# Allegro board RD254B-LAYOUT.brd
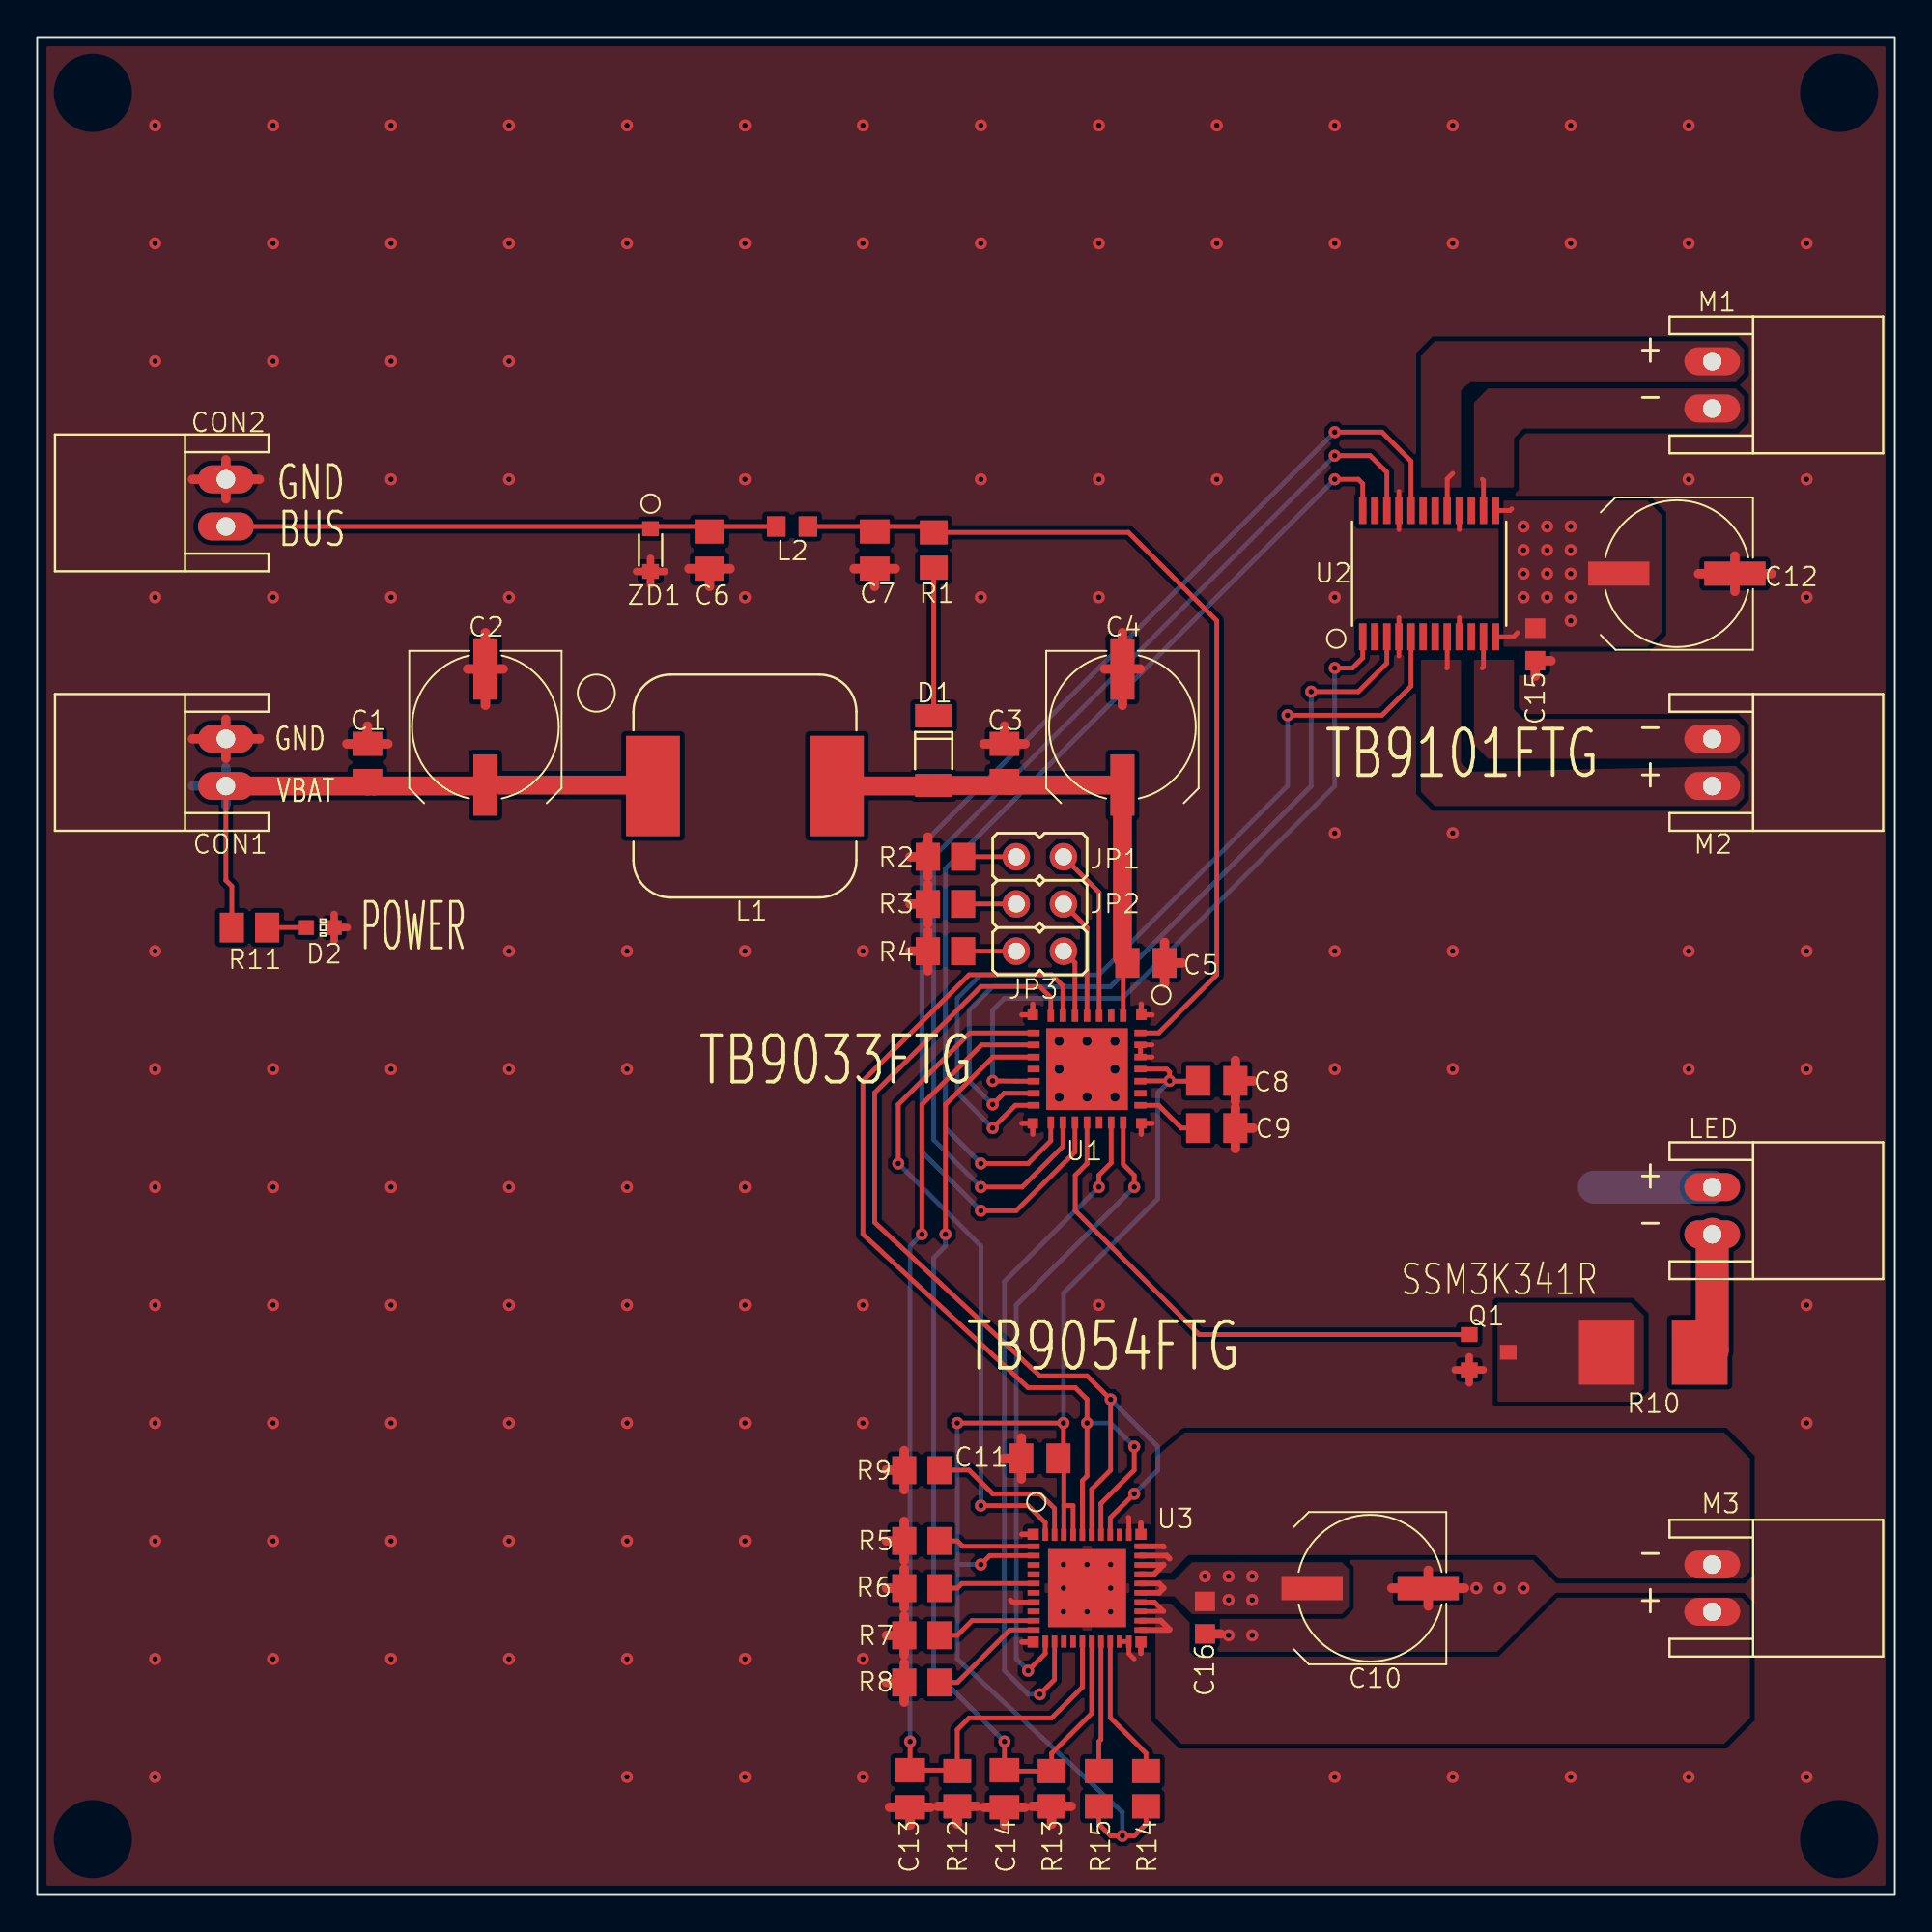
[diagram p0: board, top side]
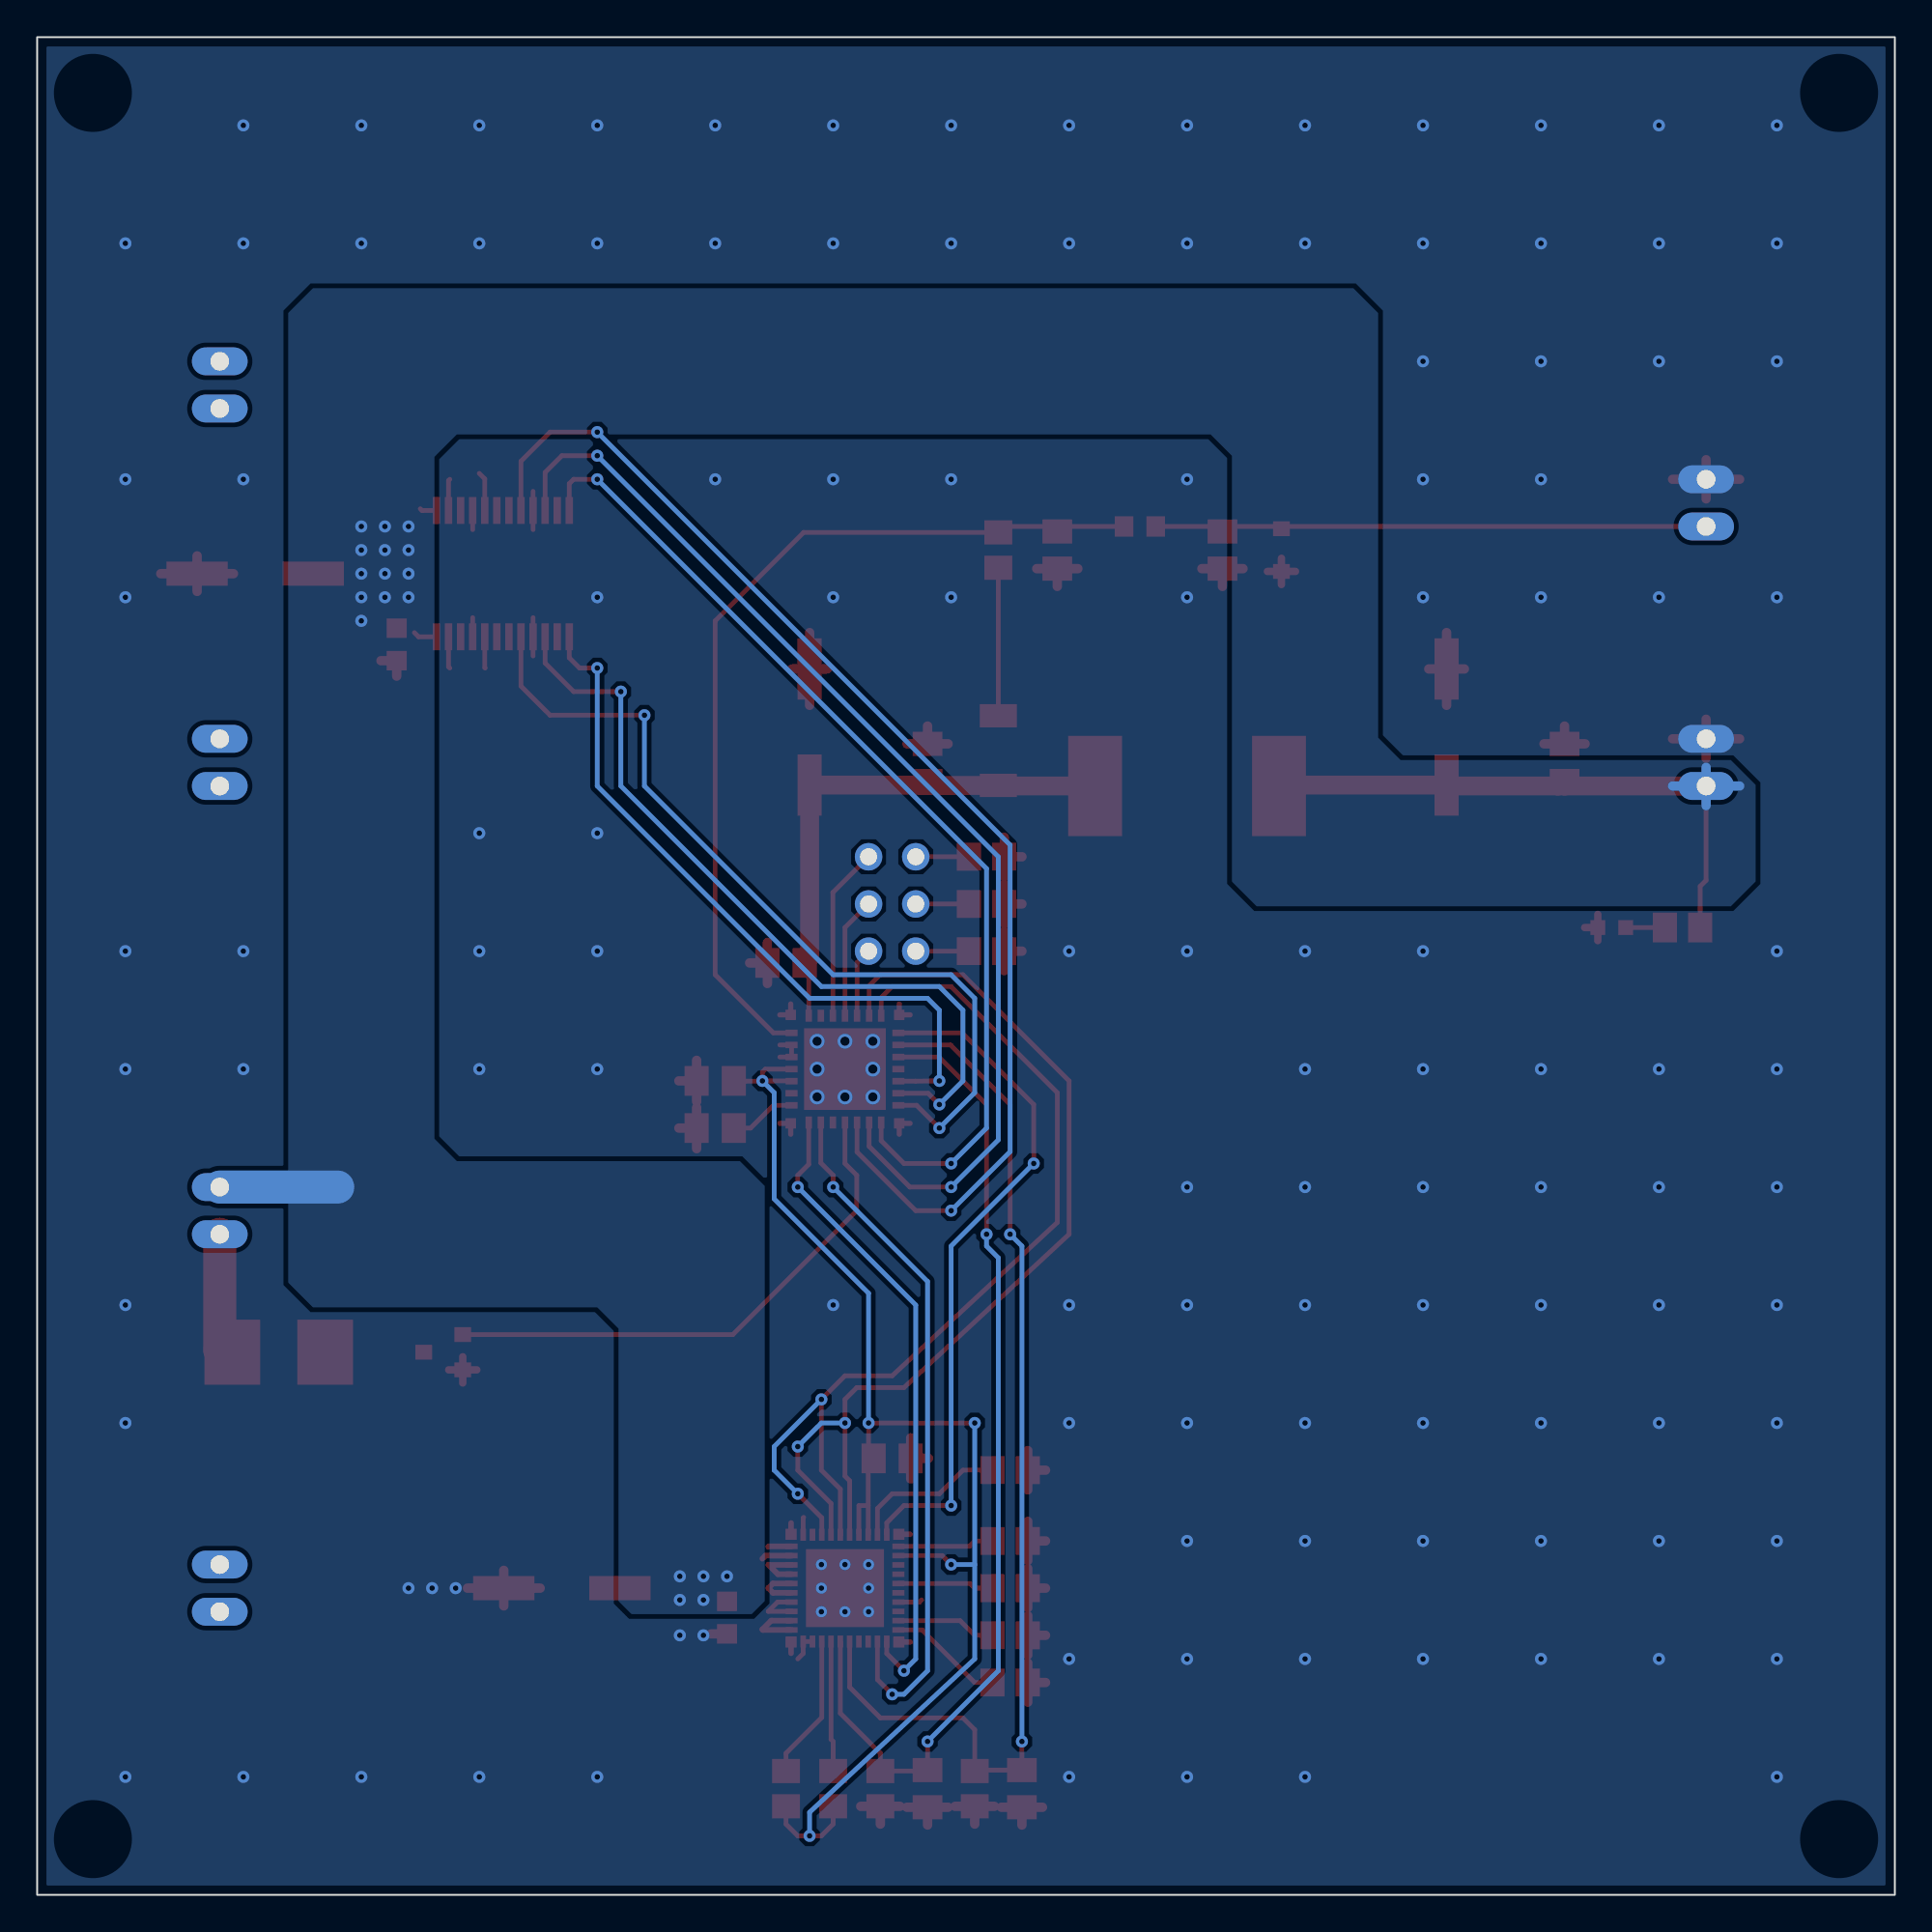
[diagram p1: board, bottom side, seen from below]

Outline 100 x 100 mm; copper layers: TOP, BOTTOM. Coordinates in mm from the lower left corner of the outline.
Outline path: rectangle 0,0 100,100

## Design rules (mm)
constraint set DEFAULT: 

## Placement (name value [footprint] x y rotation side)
C1  -  [C0805K]  17.78 60.96 90 top
C2  -  [UD_8X10_NICHICON_01]  24.13 62.87 270 top
C3  -  [C0805K]  52.07 60.96 90 top
C4  -  [UD_8X10_NICHICON_01]  58.42 62.87 270 top
C5  -  [C0805K]  59.69 50.16 0 top
C6  -  [C0805K]  36.2 72.39 270 top
C7  -  [C0805K]  45.09 72.39 270 top
C8  -  [C0805K]  63.5 43.81 180 top
C9  -  [C0805K]  63.5 41.27 180 top
C10  -  [UD_8X10_NICHICON_01]  71.75 16.51 180 top
C11  -  [C0805K]  53.98 23.5 0 top
C12  -  [UD_8X10_NICHICON_01]  88.27 71.12 180 top
C13  -  [C0805K]  46.99 5.71 270 top
C14  -  [C0805K]  52.07 5.71 270 top
C15  -  [C0603K]  80.64 67.31 270 top
C16  -  [C0603K]  62.87 14.92 270 top
CON1  -  [S2B_XH_A]  10.16 60.96 90 top
CON2  -  [S2B_XH_A]  10.16 74.93 90 top
CON3  -  [S2B_XH_A]  90.17 81.28 270 top
CON4  -  [S2B_XH_A]  90.17 60.96 270 top
CON5  -  [S2B_XH_A]  90.17 16.51 270 top
CON6  -  [S2B_XH_A]  90.17 36.83 270 top
D1  -  [LL4148]  48.26 61.59 90 top
D2  -  [CHIP_LED0603]  15.24 52.07 270 top
JP1  -  [JP1]  53.98 55.88 270 top
JP2  -  [JP1]  53.98 53.34 270 top
JP3  -  [JP1]  53.98 50.8 270 top
L1  -  [7447709222]  38.1 59.69 270 top
L2  -  [R0603]  40.64 73.66 0 top
NOREF  -  []  -70 -47 0 top
Q1  -  [SOT_23F]  78.74 29.21 270 top
R1  -  [R0805]  48.26 72.39 270 top
R2  -  [R0805]  48.9 55.88 180 top
R3  -  [R0805]  48.9 53.34 180 top
R4  -  [R0805]  48.9 50.8 180 top
R5  -  [R0805]  47.62 19.05 180 top
R6  -  [R0805]  47.62 16.51 180 top
R7  -  [R0805]  47.62 13.97 180 top
R8  -  [R0805]  47.62 11.43 180 top
R9  -  [R0805]  47.62 22.86 180 top
R10  -  [R2512_2010]  87 29.21 0 top
R11  -  [M0805]  11.43 52.07 180 top
R12  -  [R0805]  49.53 5.71 270 top
R13  -  [R0805]  54.61 5.71 270 top
R14  -  [R0805]  59.69 5.71 90 top
R15  -  [R0805]  57.15 5.71 90 top
U1  -  [P_VQFN28_0606_0_65_003_01]  56.52 44.45 180 top
U2  -  [SSOP24_P_300_0_65A]  74.93 71.12 90 top
U3  -  [P_VQFN40_0606_0_50_001_01]  56.52 16.51 270 top
ZD1  -  [USC]  33.02 72.39 270 top

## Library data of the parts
C1 C3 C5-C9 C11 C13 C14 = C0805K: alternate symbols: (T:C0805K,C1_C0805K,C3_C0805K,C5_C0805K,C6_C0805K,C7_C0805K,C8_C0805K,C9_C0805K,C11_C0805K,C13_C0805K,C14_C0805K;B:C0805K_bk)
C2 C4 C10 C12 = UD-8X10_NICHICON_01: alternate symbols: (T:UD_8X10_NICHICON_01,C2_UD_8X10_NICHICON_01,C4_UD_8X10_NICHICON_01,C10_UD_8X10_NICHICON_01,C12_UD_8X10_NICHICON_01;B:UD_8X10_NICHICON_01_bk)
C15 C16 = C0603K: alternate symbols: (T:C0603K,C15_C0603K,C16_C0603K;B:C0603K_bk)
CON1-CON6 = S2B-XH-A: alternate symbols: (T:S2B_XH_A,CON1_S2B_XH_A,CON2_S2B_XH_A,CON3_S2B_XH_A;B:S2B_XH_A_bk)
D1 = LL4148: alternate symbols: (T:LL4148;B:LL4148_bk)
D2 = CHIP-LED0603: alternate symbols: (T:CHIP_LED0603,D2_CHIP_LED0603;B:CHIP_LED0603_bk)
JP1-JP3 = JP1: alternate symbols: (T:JP1,JP1_JP1,JP2_JP1,JP3_JP1;B:JP1_bk)
L1 = 7447709222: alternate symbols: (T:7447709222;B:7447709222_bk)
L2 = R0603: alternate symbols: (T:R0603,L2_R0603;B:R0603_bk)
Q1 = SOT-23F: alternate symbols: (T:SOT_23F;B:SOT_23F_bk)
R1-R9 R12-R15 = R0805: alternate symbols: (T:R0805,R12_R0805,R13_R0805,R14_R0805,R15_R0805,R1_R0805,R2_R0805,R3_R0805,R4_R0805,R5_R0805,R6_R0805,R7_R0805,R8_R0805,R9_R0805;B:R0805_bk)
R10 = R2512-2010: alternate symbols: (T:R2512_2010,R10_R2512_2010;B:R2512_2010_bk)
R11 = M0805: alternate symbols: (T:M0805,R11_M0805;B:M0805_bk)
U1 = P-VQFN28-0606-0_65-003_01: alternate symbols: (T:P_VQFN28_0606_0_65_003_01,U1_P_VQFN28_0606_0_65_003_01;B:P_VQFN28_0606_0_65_003_01_bk)
U2 = SSOP24-P-300-0_65A: alternate symbols: (T:SSOP24_P_300_0_65A;B:SSOP24_P_300_0_65A_bk)
U3 = P-VQFN40-0606-0_50-001_01: alternate symbols: (T:P_VQFN40_0606_0_50_001_01,U3_P_VQFN40_0606_0_50_001_01;B:P_VQFN40_0606_0_50_001_01_bk)
ZD1 = USC: alternate symbols: (T:USC;B:USC_bk)

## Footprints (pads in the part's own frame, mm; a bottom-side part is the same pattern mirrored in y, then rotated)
7447709222
  rect 5.4x2.9 smd: 1(0,-4.95) 2(0,4.95)
C0603K
  rect 1.05x1.08 smd: 1(-0.875,0) 2(0.875,0)
C0805K
  rect 1.3x1.6 smd: 1(-1,0) 2(1,0)
CHIP_LED0603
  rect 0.8x0.8 smd: A(0,-0.75) C(0,0.75)
JP1
  round 1.48 hole 0.914: 1(0,-1.27) 2(0,1.27)
LL4148
  rect 1.25x2 smd: A(-1.875,0) K(1.875,0)
M0805
  rect 1.3x1.6 smd: 1(-0.95,0) 2(0.95,0)
P_VQFN28_0606_0_65_003_01
  rect 0.35x0.65 smd: 1(-1.95,-2.875) 2(-1.3,-2.875) 3(-0.65,-2.875) 4(0,-2.875) 5(0.65,-2.875) 6(1.3,-2.875) 7(1.95,-2.875) 15(1.95,2.875) 16(1.3,2.875) 17(0.65,2.875) 18(0,2.875) 19(-0.65,2.875) 20(-1.3,2.875) 21(-1.95,2.875)
  rect 0.56x0.56 smd: 1T(-2.92,-2.92) 2T(2.92,-2.92) 3T(2.92,2.92) 4T(-2.92,2.92)
  rect 0.65x0.35 smd: 8(2.875,-1.95) 9(2.875,-1.3) 10(2.875,-0.65) 11(2.875,0) 12(2.875,0.65) 13(2.875,1.3) 14(2.875,1.95) 22(-2.875,1.95) 23(-2.875,1.3) 24(-2.875,0.65) 25(-2.875,0) 26(-2.875,-0.65) 27(-2.875,-1.3) 28(-2.875,-1.95)
  rect 4.4x4.4 smd: E_PAD(0,0)
P_VQFN40_0606_0_50_001_01
  rect 0.3x0.65 smd: 1(-2.25,-2.875) 2(-1.75,-2.875) 3(-1.25,-2.875) 4(-0.75,-2.875) 5(-0.25,-2.875) 6(0.25,-2.875) 7(0.75,-2.875) 8(1.25,-2.875) 9(1.75,-2.875) 10(2.25,-2.875) 21(2.25,2.875) 22(1.75,2.875) 23(1.25,2.875) 24(0.75,2.875) 25(0.25,2.875) 26(-0.25,2.875) 27(-0.75,2.875) 28(-1.25,2.875) 29(-1.75,2.875) 30(-2.25,2.875)
  rect 0.6x0.6 smd: 1T(2.9,-2.9) 2T(2.9,2.9) 3T(-2.9,2.9) 4T(-2.9,-2.9)
  rect 0.65x0.3 smd: 11(2.875,-2.25) 12(2.875,-1.75) 13(2.875,-1.25) 14(2.875,-0.75) 15(2.875,-0.25) 16(2.875,0.25) 17(2.875,0.75) 18(2.875,1.25) 19(2.875,1.75) 20(2.875,2.25) 31(-2.875,2.25) 32(-2.875,1.75) 33(-2.875,1.25) 34(-2.875,0.75) 35(-2.875,0.25) 36(-2.875,-0.25) 37(-2.875,-0.75) 38(-2.875,-1.25) 39(-2.875,-1.75) 40(-2.875,-2.25)
  rect 4.2x4.2 smd: E_PAD(0,0)
R0603
  rect 1x1.1 smd: 1(-0.85,0) 2(0.85,0)
R0805
  rect 1.3x1.5 smd: 1(-0.95,0) 2(0.95,0)
R2512_2010
  rect 3x3.5 smd: P_1(-2.5,0) P_2(2.5,0)
S2B_XH_A
  oval 1.5x3 hole 1: 1(1.27,0) 2(-1.27,0)
SOT_23F
  rect 0.8x0.9 smd: 1(-0.95,-1.65) 2(0.95,-1.65) 3(0,0.45)
SSOP24_P_300_0_65A
  rect 1.45x0.4 smd: 1(-3.4,3.575) 2(-3.4,2.925) 3(-3.4,2.275) 4(-3.4,1.625) 5(-3.4,0.975) 6(-3.4,0.325) 7(-3.4,-0.325) 8(-3.4,-0.975) 9(-3.4,-1.625) 10(-3.4,-2.275) 11(-3.4,-2.925) 12(-3.4,-3.575) 13(3.4,-3.575) 14(3.4,-2.925) 15(3.4,-2.275) 16(3.4,-1.625) 17(3.4,-0.975) 18(3.4,-0.325) 19(3.4,0.325) 20(3.4,0.975) 21(3.4,1.625) 22(3.4,2.275) 23(3.4,2.925) 24(3.4,3.575)
UD_8X10_NICHICON_01
  rect 3.3x1.3 smd: 1(-3.125,0) 2(3.125,0)
USC
  rect 0.8x0.9 smd: 1(-1.15,0) 2(1.15,0)

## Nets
+12V: C1.1 C2.2 C10.2 C12.2 C15.1 C16.1 CON1.2 CON6.2 L1.1 R11.2 U2.12 U2.13 U3.25 U3.26
GND: C1.2 C2.1 C3.2 C4.1 C5.2 C6.2 C7.2 C8.1 C9.1 C10.1 C11.1 C12.1 C13.2 C14.2 C15.2 C16.2 CON1.1 CON2.1 D2.C Q1.2 R2.2 R3.2 R4.2 R5.2 R6.2 R7.2 R8.2 R9.2 R12.2 R13.2 U1.1T U1.2T U1.3T U1.4T U1.26 U1.27 U1.E_PAD U2.4 U2.9 U2.16 U2.21 U3.1T U3.2T U3.3T U3.4T U3.7 U3.19 U3.20 U3.31 U3.32 U3.E_PAD ZD1.2
VCC: C8.2 C11.2 R14.1 R15.1 U1.24 U1.25 U3.2 U3.37 U3.38
VDD: C9.2 U1.22
BUS: C3.1 C4.2 C5.1 C6.1 C7.1 CON2.2 D1.A D1.K L1.2 L2.1 L2.2 R1.1 R1.2 U1.1 U1.28 ZD1.1
N_2: JP3.1 JP3.2 R4.1 U1.5
N_3: JP2.1 JP2.2 R3.1 U1.4
N_4: JP1.1 JP1.2 R2.1 U1.3
N_5: R5.1 U3.1
N_6: R6.1 U3.5
N_7: R7.1 U3.9
N_8: R8.1 U3.10
N_9: CON4.1 U2.8
N_10: CON5.2 U3.27 U3.28 U3.29 U3.30
N_11: CON5.1 U3.21 U3.22 U3.23 U3.24
N_12: U1.7 U3.33 U3.35
N_13: U1.6 U3.34 U3.36
N_14: U1.8 U3.40
N_15: R9.1 U3.39
N_16: CON4.2 U2.11
N_17: C13.1 R12.1 U1.9 U3.15
N_18: C14.1 R13.1 U1.10 U3.16
N_19: U1.21 U3.11
N_20: U1.20 U3.12
N_21: CON6.1 R10.P_2
N_22: U1.14 U2.5
N_23: U1.13 U2.3
N_24: U1.12 U2.1
N_25: U1.15 U2.24
N_26: U1.16 U2.22
N_27: U1.17 U2.20
N_28: CON3.1 U2.14
N_29: CON3.2 U2.17
N_30: D2.A R11.1
N_31: Q1.3 R10.P_1
N_32: Q1.1 U1.18
N_36: R14.2 U3.18
N_37: R15.2 U3.17

Pads without a net: U1 2 11 19 23; U2 2 6 7 10 15 18 19 23; U3 3 4 6 8 13 14

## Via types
v1: diameter 0.65, hole 0.3, TOP to BOTTOM, 169 vias
v2: diameter 0.803, hole 0.5, TOP to BOTTOM, 8 vias
v3: diameter 0.6, hole 0.3, TOP to BOTTOM, 8 vias

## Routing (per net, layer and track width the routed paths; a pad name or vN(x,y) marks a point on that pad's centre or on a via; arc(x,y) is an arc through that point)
+12V: length 48.4
  TOP w0.254: 78.5,67.72 79.47,67.72 79.69,67.94 ; 78.5,74.52 79.28,74.52 79.38,74.61 ; CON1.2 10.16,54.61 10.48,54.29 R11.2
  TOP w0.305: U3.26 60.39,16.76 60.64,16.51 60.39,16.26 U3.25
  TOP w1.016: L1.1 33.1,59.74 C2.2 24.08,59.69 18.14,59.69 ; 17.78,59.69 C1.1 18.14,59.69 ; 17.78,59.69 CON1.2 ; 17.78,59.69 18.14,59.69
  BOTTOM w0.5: CON1.2 11.96,59.69 ; CON1.2 10.16,58.63 ; CON1.2 10.16,60.69 ; CON1.2 8.36,59.69
  BOTTOM w1.778: CON6.2 83.82,38.1
  vias: v1(62.87,17.14) v1(64.14,17.14) v1(64.14,15.88) v1(65.41,17.14) v1(65.41,15.88) v1(80.01,73.66) v1(80.01,72.39) v1(80.01,71.12) v1(80.01,69.85) v1(81.28,73.66) v1(81.28,72.39) v1(81.28,71.12) v1(81.28,69.85) v1(82.55,73.66) v1(82.55,72.39) v1(82.55,71.12) v1(82.55,69.85) v1(82.55,68.58)
GND: length 126.5
  TOP w0.254: U3.31 58.77,20.29 58.74,20.32 ; 60.02,45.75 U1.27 U1.26 60.02,45.1 ; 73.31,75.55 U2.21 73.31,73.49 ; 76.56,73.49 U2.16 ; 59.05,12.7 58.77,12.99 U3.20 58.29,13.63 ; 73.31,66.69 U2.4 73.31,68.75 ; 52.39,15.88 52.5,15.76 U3.7 ; U2.9 76.56,68.75
  TOP w0.28: 53.01,41.53 U1.3T 53.59,40.95 ; 60.02,47.37 U1.1T 59.44,47.95 ; 53.59,47.95 U1.2T 53.01,47.37 ; 60.02,41.53 U1.4T 59.44,40.95
  TOP w0.3: 59.41,13.01 U3.2T ; U3.3T 59.41,20.02 ; 53.01,19.41 U3.4T ; 53.01,13.61 U3.1T
  TOP w0.4: 76.33,28.26 Q1.2 ; Q1.2 77.09,28.96 ; Q1.2 77.09,27.55 ; Q1.2 77.84,28.26 ; ZD1.2 33.77,71.24 ; ZD1.2 32.27,71.24 ; ZD1.2 33.02,71.94 ; ZD1.2 33.02,70.53 ; D2.C 15.99,52.77 ; D2.C 15.99,51.37 ; D2.C 16.7,52.07
  TOP w0.5: 8.36,62.23 CON1.1 ; CON1.1 10.16,61.17 ; CON1.1 10.16,63.28 ; CON1.1 11.96,62.23 ; CON2.1 11.96,76.2 ; CON2.1 10.16,77.25 ; CON2.1 10.16,75.14 ; CON2.1 8.36,76.2
  TOP w0.508: 45.72,13.97 R7.2 ; R7.2 46.67,15.03 ; R7.2 46.67,12.91 ; C12.1 93.34,71.12 ; C12.1 91.39,70.17 ; C12.1 91.39,72.08 ; C12.1 89.44,71.12 ; 45.72,22.86 R9.2 ; R9.2 46.67,21.8 ; R9.2 46.67,23.91 ; 45.72,19.05 R5.2 ; R5.2 46.67,18 ; R5.2 46.67,20.11 ; 47.95,52.28 R3.2 ; R3.2 47.95,54.4 ; R3.2 46.99,53.34 ; 16.68,61.96 C1.2 ; C1.2 18.89,61.96 ; C1.2 17.78,62.91 ; 72.92,16.51 C10.1 ; C10.1 74.88,15.55 ; C10.1 74.88,17.46 ; C10.1 76.83,16.51 ; 35.09,71.39 C6.2 ; C6.2 37.3,71.39 ; C6.2 36.2,70.44 ; C3.2 52.07,62.91 ; C3.2 50.97,61.96 ; C3.2 53.17,61.96 ; C16.2 63.71,14.05 ; C7.2 46.19,71.39 ; C7.2 45.09,70.44 ; C7.2 43.98,71.39 ; R2.2 47.95,56.94 ; R2.2 46.99,55.88 ; R2.2 47.95,54.83 ; C4.1 59.38,65.99 ; C4.1 58.42,64.03 ; C4.1 57.47,65.99 ; C4.1 58.42,67.94 ; C8.1 65.45,43.81 ; C8.1 64.5,44.92 ; C8.1 64.5,42.71 ; 47.95,49.74 R4.2 ; R4.2 46.99,50.8 ; R4.2 47.95,51.85 ; R12.2 50.59,4.76 ; R12.2 48.48,4.76 ; R12.2 49.53,3.81 ; C2.1 25.09,65.99 ; C2.1 24.13,67.94 ; C2.1 24.13,64.03 ; C2.1 23.18,65.99 ; 46.67,15.46 R6.2 ; R6.2 46.67,17.57 ; R6.2 45.72,16.51 ; 45.72,11.43 R8.2 ; R8.2 46.67,10.38 ; R8.2 46.67,12.48 ; 60.69,49.06 C5.2 ; C5.2 61.65,50.16 ; C5.2 60.69,51.27 ; C11.1 52.98,24.6 ; C11.1 52.02,23.5 ; C11.1 52.98,22.39 ; 50.97,4.71 C14.2 ; C14.2 52.07,3.76 ; C14.2 53.17,4.71 ; 54.61,3.81 R13.2 ; R13.2 55.66,4.76 ; R13.2 53.55,4.76 ; C9.1 64.5,42.38 ; C9.1 64.5,40.17 ; C9.1 65.45,41.27 ; 45.88,4.71 C13.2 ; C13.2 46.99,3.76 ; C13.2 48.09,4.71 ; 80.64,65.61 C15.2 81.49,66.44
  vias: v1(6.35,95.25) v1(6.35,88.9) v1(6.35,82.55) v1(6.35,69.85) v1(6.35,50.8) v1(6.35,44.45) v1(6.35,38.1) v1(6.35,31.75) v1(6.35,25.4) v1(6.35,19.05) v1(6.35,12.7) v1(6.35,6.35) v1(12.7,95.25) v1(12.7,88.9) v1(12.7,82.55) v1(12.7,69.85) v1(12.7,44.45) v1(12.7,38.1) v1(12.7,31.75) v1(12.7,25.4) v1(12.7,19.05) v1(12.7,12.7) v1(19.05,95.25) v1(19.05,88.9) v1(19.05,82.55) v1(19.05,76.2) v1(19.05,69.85) v1(19.05,44.45) v1(19.05,38.1) v1(19.05,31.75) v1(19.05,25.4) v1(19.05,19.05) v1(19.05,12.7) v1(25.4,95.25) v1(25.4,88.9) v1(25.4,82.55) v1(25.4,76.2) v1(25.4,69.85) v1(25.4,50.8) v1(25.4,44.45) v1(25.4,38.1) v1(25.4,31.75) v1(25.4,25.4) v1(25.4,19.05) v1(25.4,12.7) v1(31.75,95.25) v1(31.75,88.9) v1(31.75,50.8) v1(31.75,44.45) v1(31.75,38.1) v1(31.75,31.75) v1(31.75,25.4) v1(31.75,19.05) v1(31.75,12.7) v1(31.75,6.35) v1(38.1,95.25) v1(38.1,88.9) v1(38.1,76.2) v1(38.1,69.85) v1(38.1,50.8) v1(38.1,38.1) v1(38.1,31.75) v1(38.1,25.4) v1(38.1,19.05) v1(38.1,12.7) v1(38.1,6.35) v1(44.45,95.25) v1(44.45,88.9) v1(44.45,50.8) v1(44.45,31.75) v1(44.45,25.4) v1(44.45,12.7) v1(44.45,6.35) v1(50.8,95.25) v1(50.8,88.9) v1(50.8,76.2) v1(50.8,69.85) v1(57.15,95.25) v1(57.15,88.9) v1(57.15,76.2) v1(57.15,69.85) v1(57.15,31.75) v1(63.5,95.25) v1(63.5,88.9) v1(63.5,76.2) v1(64.14,13.97) v1(65.41,13.97) v1(69.85,95.25) v1(69.85,88.9) v1(69.85,69.85) v1(69.85,57.15) v1(69.85,50.8) v1(69.85,44.45) v1(69.85,6.35) v1(76.2,95.25) v1(76.2,88.9) v1(76.2,57.15) v1(76.2,50.8) v1(76.2,44.45) v1(76.2,6.35) v1(77.47,16.51) v1(78.74,16.51) v1(80.01,16.51) v1(82.55,95.25) v1(82.55,88.9) v1(82.55,6.35) v1(88.9,95.25) v1(88.9,88.9) v1(88.9,76.2) v1(88.9,50.8) v1(88.9,44.45) v1(88.9,6.35) v1(95.25,88.9) v1(95.25,76.2) v1(95.25,69.85) v1(95.25,50.8) v1(95.25,44.45) v1(95.25,31.75) v1(95.25,25.4) v1(95.25,6.35) v2(55.02,45.95) v2(55.02,44.45) v2(55.02,42.95) v2(56.52,45.95) v2(56.52,42.95) v2(58.02,45.95) v2(58.02,44.45) v2(58.02,42.95) v3(55.24,17.78) v3(55.24,16.51) v3(55.24,15.24) v3(56.52,17.78) v3(56.52,15.24) v3(57.78,17.78) v3(57.78,16.51) v3(57.78,15.24)
VCC: length 75.4
  TOP w0.254: R15.1 57.15,3.81 57.78,3.17 v1(58.42,3.17) 59.05,3.17 59.69,3.81 R14.1 ; U3.38 55.27,20.95 ; 55.27,20.95 55.27,22.84 54.98,23.13 C11.2 55.24,23.77 v1(55.24,25.4) v1(49.53,25.4) ; 55.27,20.95 55.77,20.95 U3.37 ; v1(60.96,43.81) 60.96,44.29 60.8,44.45 U1.25 ; v1(60.96,43.81) 59.39,43.81 U1.24 ; v1(60.96,43.81) 60.98,43.8 61.85,43.8 C8.2 ; v1(50.8,17.78) 51.28,18.26 U3.2
  BOTTOM w0.254: 49.53,17.78 49.53,12.7 58.42,4.45 v1(58.42,3.17) ; 49.53,17.78 v1(49.53,25.4) ; 49.53,17.78 v1(50.8,17.78) ; v1(55.24,25.4) 55.24,32.38 60.33,37.47 60.33,43.18 v1(60.96,43.81)
VDD: length 3.6
  TOP w0.254: C9.2 61.59,41.27 60.37,42.5 U1.22
BUS: length 116.6
  TOP w0.254: 58.42,50.44 C5.1 58.47,49.94 U1.1 ; CON2.2 32.9,73.66 ZD1.1 33.02,73.66 35.92,73.66 C6.1 36.56,73.39 36.83,73.66 L2.1 ; 44.45,73.66 L2.2 ; 44.45,73.66 44.81,73.66 ; 44.45,73.66 44.72,73.39 C7.1 44.81,73.66 ; 44.81,73.66 47.94,73.66 R1.1 58.74,73.34 63.5,68.58 63.5,49.53 60.37,46.4 U1.28 ; D1.K R1.2
  TOP w1.016: L1.2 48.23,59.69 D1.A 52.47,59.72 C3.1 52.29,59.74 C4.2 58.42,50.44
N_2: length 6.6
  TOP w0.254: 49.84,50.8 JP3.1 ; 55.24,50.8 55.87,50.18 U1.5
N_3: length 9.4
  TOP w0.254: 49.84,53.34 JP2.1 ; 55.24,53.34 56.52,52.07 U1.4
N_4: length 12.2
  TOP w0.254: 49.84,55.88 JP1.1 ; 55.24,55.88 57.16,53.96 U1.3
N_5: length 5.2
  TOP w0.254: R5.1 49.53,19.05 49.82,18.76 U3.1
N_6: length 5.2
  TOP w0.254: R6.1 49.53,16.51 49.78,16.76 U3.5
N_7: length 5.4
  TOP w0.254: U3.9 50.32,14.76 49.53,13.97 R7.1
N_8: length 6.2
  TOP w0.254: U3.10 52.36,14.26 49.53,11.43 R8.1
N_9: length 1.7
  TOP w0.254: 75.88,66.04 75.91,66.06 U2.8
N_10: length 5.6
  TOP w0.305: 60.64,18.73 60.62,18.76 U3.30 ; U3.27 60.12,17.26 60.62,17.76 ; 60.96,18.1 60.8,18.26 U3.29 ; 60.62,17.76 U3.28 ; 60.62,17.76 60.64,17.78
N_11: length 6.1
  TOP w0.254: U3.23 60.64,15.26 60.14,15.76 U3.24
  TOP w0.305: U3.22 60.49,14.76 60.96,14.29 60.93,14.26 U3.21
N_12: length 53.6
  TOP w0.254: v1(59.05,21.59) 57.77,20.3 U3.33 ; U3.35 56.77,21.84 57.78,22.86 v1(57.78,26.67) 56.52,27.94 53.98,27.94 45.09,36.2 45.09,43.18 50.8,48.9 53.98,48.9 54.56,48.3 U1.7
  BOTTOM w0.254: v1(57.78,26.67) 60.33,24.13 60.33,22.86 v1(59.05,21.59)
N_13: length 54.7
  TOP w0.254: U1.6 55.22,48.92 54.61,49.53 50.16,49.53 44.45,43.81 44.45,35.56 53.34,27.3 55.88,27.3 56.52,26.67 v1(56.52,25.4) 56.52,22.54 56.27,22.29 U3.36 ; v1(59.05,24.13) 59.05,22.86 57.27,21.07 U3.34
  BOTTOM w0.254: v1(59.05,24.13) 57.78,25.4 v1(56.52,25.4)
N_14: length 36.8
  TOP w0.254: v1(46.35,39.37) 46.35,42.55 50.21,46.4 U1.8 ; U3.40 54.27,20.03 53.34,20.95 v1(50.8,20.95)
  BOTTOM w0.254: v1(50.8,20.95) 50.8,34.92 v1(46.35,39.37)
N_15: length 8.5
  TOP w0.254: R9.1 50.16,22.86 51.44,21.59 53.98,21.59 54.77,20.8 U3.39
N_16: length 1.7
  TOP w0.254: U2.11 77.86,66.11 77.79,66.04
N_17: length 58.3
  TOP w0.254: U1.9 50.83,45.75 47.62,42.55 v1(47.62,35.56) ; v1(46.99,8.26) C13.1 49.53,6.71 ; 49.53,6.71 49.53,8.89 50.16,9.53 54.61,9.53 56.27,11.18 U3.15 ; 49.53,6.71 R12.1
  BOTTOM w0.254: v1(47.62,35.56) 46.99,34.92 v1(46.99,8.26)
N_18: length 53.9
  TOP w0.254: U1.10 51.45,45.1 48.9,42.55 v1(48.9,35.56) ; U3.16 56.77,9.78 54.61,7.62 R13.1 52.12,6.67 C14.1 v1(52.07,8.26)
  BOTTOM w0.254: v1(52.07,8.26) 48.26,12.06 48.26,34.29 48.9,34.92 v1(48.9,35.56)
N_19: length 34.6
  TOP w0.254: v1(53.34,12.06) 54.27,12.99 U3.11 ; v1(59.05,38.1) 59.05,38.73 58.47,39.33 U1.21
  BOTTOM w0.254: v1(59.05,38.1) 52.7,31.75 52.7,12.7 v1(53.34,12.06)
N_20: length 37.5
  TOP w0.254: v1(57.15,38.1) 57.15,38.73 57.81,39.4 U1.20 ; v1(53.98,10.79) 54.77,11.59 U3.12
  BOTTOM w0.254: v1(53.98,10.79) 53.34,10.79 52.07,12.06 52.07,33.02 v1(57.15,38.1)
N_21: length 6.9
  TOP w1.778: R10.P_2 90.17,29.34 CON6.1
N_22: length 46.8
  TOP w0.254: v1(67.31,63.5) 72.39,63.5 73.95,65.06 U2.5 ; v1(51.44,41.27) 52.66,42.5 U1.14
  BOTTOM w0.254: v1(51.44,41.27) 49.53,43.18 49.53,48.26 50.8,49.53 57.15,49.53 67.31,59.69 v1(67.31,63.5)
N_23: length 42.7
  TOP w0.254: U2.3 72.66,66.31 71.12,64.77 v1(68.58,64.77) ; v1(51.44,42.55) 52.04,43.15 U1.13
  BOTTOM w0.254: v1(51.44,42.55) 50.16,43.81 50.16,47.62 51.44,48.9 57.78,48.9 68.58,59.69 v1(68.58,64.77)
N_24: length 38.6
  TOP w0.254: U2.1 71.36,66.59 70.8,66.04 v1(69.85,66.04) ; U1.12 52.72,43.8 v1(51.44,43.81)
  BOTTOM w0.254: v1(51.44,43.81) 51.44,47.62 52.07,48.26 58.42,48.26 69.85,59.69 v1(69.85,66.04)
N_25: length 54.6
  TOP w0.254: U1.15 54.56,40.59 53.34,39.37 v1(50.8,39.37) ; U2.24 71.36,75.97 71.12,76.2 v1(69.85,76.2)
  BOTTOM w0.254: v1(50.8,39.37) 48.9,41.27 48.9,55.24 v1(69.85,76.2)
N_26: length 61.2
  TOP w0.254: v1(69.85,77.47) 71.75,77.47 72.66,76.57 U2.22 ; v1(50.8,38.1) 53.02,38.1 55.22,40.29 U1.16
  BOTTOM w0.254: v1(69.85,77.47) 48.26,55.88 48.26,40.64 v1(50.8,38.1)
N_27: length 67.8
  TOP w0.254: U2.20 73.95,77.17 72.39,78.74 v1(69.85,78.74) ; U1.17 55.87,39.99 52.7,36.83 v1(50.8,36.83)
  BOTTOM w0.254: v1(50.8,36.83) 47.62,40.01 47.62,56.52 v1(69.85,78.74)
N_28: length 1.7
  TOP w0.254: U2.14 77.86,76.13 77.79,76.2
N_29: length 2.1
  TOP w0.254: U2.17 75.91,76.22 76.2,76.52
N_30: length 2.1
  TOP w0.254: R11.1 D2.A
N_32: length 29
  TOP w0.254: Q1.1 62.55,30.16 55.88,36.83 55.88,38.73 56.52,39.37 U1.18
N_36: length 7.8
  TOP w0.254: U3.18 57.77,9.54 59.69,7.62 R14.2
N_37: length 7
  TOP w0.254: U3.17 57.27,8.37 57.15,8.26 R15.2

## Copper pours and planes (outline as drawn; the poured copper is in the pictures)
+12V on TOP: 79.01,67.18 78.95,67.2 78.93,67.26 78.93,74.98 78.95,75.04 79.01,75.06 86.65,75.06 86.68,75.05 86.7,75.03 87.42,74.32 87.43,74.29 87.44,74.26 87.44,67.98 87.43,67.95 87.42,67.92 86.7,67.2 86.68,67.19 86.65,67.18
+12V on BOTTOM: 60.83,38.13 60.84,38.16 60.85,38.19 62.14,39.48 62.17,39.49 62.2,39.5 77.41,39.5 78.61,40.7 78.61,77.41 77.41,78.61 70.48,78.61 70.43,78.63 70.4,78.69 70.4,78.97 70.08,79.29 69.62,79.29 69.3,78.97 69.3,78.72 69.29,78.7 69.27,78.67 69.24,78.64 69.21,78.62 69.18,78.61 36.83,78.61 35.69,77.47 35.69,54.58 35.68,54.55 35.66,54.52 34.38,53.23 34.35,53.22 34.32,53.21 8.86,53.21 8.83,53.22 8.8,53.23 7.51,54.52 7.5,54.55 7.49,54.58 7.49,59.72 7.5,59.75 7.51,59.78 8.8,61.06 8.83,61.08 8.86,61.09 26.61,61.09 27.81,62.29 27.81,85.12 27.82,85.15 27.84,85.18 29.12,86.47 29.15,86.48 29.18,86.49 85.12,86.49 85.15,86.48 85.18,86.47 86.47,85.18 86.48,85.15 86.49,85.12 86.49,32.99 86.48,32.96 86.47,32.93 85.18,31.64 85.15,31.63 85.12,31.62 69.85,31.62 68.71,30.48 68.71,15.84 68.7,15.81 68.69,15.79 68.03,15.13 68.01,15.12 67.98,15.11 61.56,15.11 61.53,15.12 61.51,15.13 60.85,15.79 60.84,15.81 60.83,15.84 ; 1 cut-out
GND on TOP: 54.3,16.26 54.25,16.28 54.23,16.33 54.23,16.69 54.25,16.74 54.3,16.76 54.53,16.76 54.59,16.74 54.61,16.69 54.61,16.33 54.59,16.28 54.53,16.26
GND on TOP: 99.5,0.57 99.48,0.52 99.43,0.5 0.57,0.5 0.52,0.52 0.5,0.57 0.5,99.43 0.52,99.48 0.57,99.5 99.43,99.5 99.48,99.48 99.5,99.43 ; 20 cut-outs
GND on TOP: 58.49,16.26 58.44,16.28 58.42,16.33 58.42,16.69 58.44,16.74 58.49,16.76 58.73,16.76 58.78,16.74 58.8,16.69 58.8,16.33 58.78,16.28 58.73,16.26
GND on TOP: 56.34,14.22 56.28,14.25 56.26,14.3 56.26,14.59 56.28,14.65 56.34,14.67 56.69,14.67 56.75,14.65 56.77,14.59 56.77,14.3 56.75,14.25 56.69,14.22
GND on TOP: 73.11,75.5 73.06,75.52 73.04,75.57 73.04,76.57 73.01,76.72 72.92,76.84 72.02,77.74 71.9,77.82 71.75,77.85 70.28,77.85 70.25,77.86 70.23,77.87 70.1,78 70.09,78.03 70.08,78.06 70.08,78.15 70.09,78.18 70.1,78.21 70.23,78.34 70.25,78.35 70.28,78.36 72.2,78.36 72.23,78.35 72.25,78.34 73.55,77.04 73.57,77.01 73.57,76.99 73.57,75.57 73.55,75.52 73.5,75.5
GND on BOTTOM: 60.48,24.55 60.45,24.55 60.42,24.57 58.36,26.63 58.34,26.66 58.34,26.69 58.34,26.9 58.01,27.22 57.56,27.22 57.23,26.9 57.23,26.44 57.56,26.12 57.77,26.12 57.8,26.11 57.82,26.09 58,25.92 58.01,25.9 58.02,25.87 58.02,25.83 57.99,25.77 57.92,25.76 57.85,25.78 57.78,25.78 56.95,25.78 56.92,25.79 56.9,25.8 56.74,25.95 56.29,25.95 55.96,25.63 55.93,25.61 55.9,25.6 55.86,25.6 55.83,25.61 55.8,25.63 55.65,25.78 55.63,25.8 55.63,25.83 55.63,32.2 55.63,32.22 55.65,32.25 60.45,37.05 60.47,37.06 60.5,37.07 60.56,37.05 60.58,36.99 60.58,24.62 60.56,24.57 60.5,24.55
GND on BOTTOM: 99.5,0.57 99.48,0.52 99.43,0.5 0.57,0.5 0.52,0.52 0.5,0.57 0.5,99.43 0.52,99.48 0.57,99.5 99.43,99.5 99.48,99.48 99.5,99.43 ; 20 cut-outs
N_10 on TOP: 81.95,17.02 81.92,17.02 81.89,17.04 80.64,18.29 61.98,18.29 61.05,17.36 61.02,17.34 60.99,17.34 60.27,17.34 60.22,17.36 60.2,17.41 60.2,23.52 60.21,23.56 60.22,23.58 61.76,24.87 61.79,24.89 61.81,24.89 62.29,24.89 90.78,24.89 90.8,24.88 90.83,24.87 92.18,23.52 92.2,23.49 92.2,23.46 92.2,17.43 92.2,17.4 92.18,17.38 91.84,17.04 91.82,17.02 91.79,17.02
N_11 on TOP: 61.63,8.13 61.6,8.13 61.57,8.15 60.22,9.5 60.2,9.53 60.2,9.56 60.2,15.61 60.22,15.66 60.27,15.68 60.99,15.68 61.02,15.68 61.05,15.66 62.02,14.69 62.03,14.67 62.04,14.64 62.04,13.08 62.29,12.83 78.68,12.83 81.83,15.98 81.85,16 81.88,16 91.73,16 91.76,16 91.78,15.98 92.18,15.58 92.2,15.56 92.2,15.53 92.2,9.56 92.2,9.53 92.18,9.5 90.83,8.15 90.8,8.13 90.77,8.13
N_31 on TOP: 78.69,26.54 78.63,26.56 78.61,26.62 78.61,31.8 78.63,31.86 78.69,31.88 85.76,31.88 85.79,31.87 85.81,31.86 86.47,31.2 86.48,31.18 86.49,31.15 86.49,27.27 86.48,27.24 86.47,27.22 85.81,26.57 85.79,26.55 85.76,26.54

Small or netless copper shapes (teardrops, artwork), in the pictures only: 6 on TOP

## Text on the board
Ref Des/Silkscreen Top: GND | VBAT | CON2 | CON1 | R11 | D2 | C1 | C2 | ZD1 | C6 | L1 | L2 | R9 | R6 | R5 | R7 | R8 | C7 | R2 | R3 | R4 | D1 | R1 | C11 | C3 | JP3 | U1 | JP1 | JP2 | C4 | U3 | C5 | C8 | C9 | U2 | C10 | Q1 | R10 | LED | M2 | M1 | M3 | C12 | C13 | R12 | C14 | R13 | R15 | R14 | C16 | C15 | + | - | POWER | SSM3K341R | BUS | TB9033FTG | TB9054FTG | TB9101FTG
SYMBOL-1-TOP: VALUE
SYMBOL-2-TOP: VALUE
